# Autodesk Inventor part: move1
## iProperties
Author: Administrator
Created: 2000-12
Part Number: move1
Document SubType Name: Modeling
Designer: Administrator
Control State: 0
Master: False
Checked Out: False
PropertySet Name: Design Tracking Control
Shininess: 0.0
PropertySet Name: _Private Model Information
Density: 0.0
Volumn: 0.0
Area: 0.0
PropertySet Name: Model Information
